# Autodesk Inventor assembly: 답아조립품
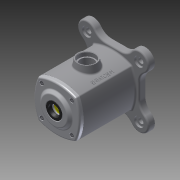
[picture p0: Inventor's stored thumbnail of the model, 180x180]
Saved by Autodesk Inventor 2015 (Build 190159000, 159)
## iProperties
Created: 2016-05
Part Number: 답아조립품
Document SubType Name: Assembly
Designer: Administrator
Author: Administrator
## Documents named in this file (6)
- C:\Users\Administrator\Desktop\460507V1006\답안조립품.iam
- C:\Users\Administrator\Desktop\460507V1006\본체.ipt
- C:\Users\Administrator\Desktop\460507V1006\베어링-6203.ipt
- C:\Users\Administrator\Desktop\460507V1006\오일실.ipt
- C:\Users\Administrator\Desktop\460507V1006\커버.ipt
- C:\Users\Administrator\Desktop\460507V1006\M4x0.7x12.ipt
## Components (8 placed, 1 different names)
1. M4x0.7x12:1 — 각도:1
2. M4x0.7x12:2
3. M4x0.7x12:3
4. M4x0.7x12:4
5. M4x0.7x12:5 — 각도:2
6. M4x0.7x12:6
7. M4x0.7x12:7
8. M4x0.7x12:8
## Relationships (2: Angle 2)
- 각도:1 [Angle]: M4x0.7x12:1
- 각도:2 [Angle]: M4x0.7x12:5
